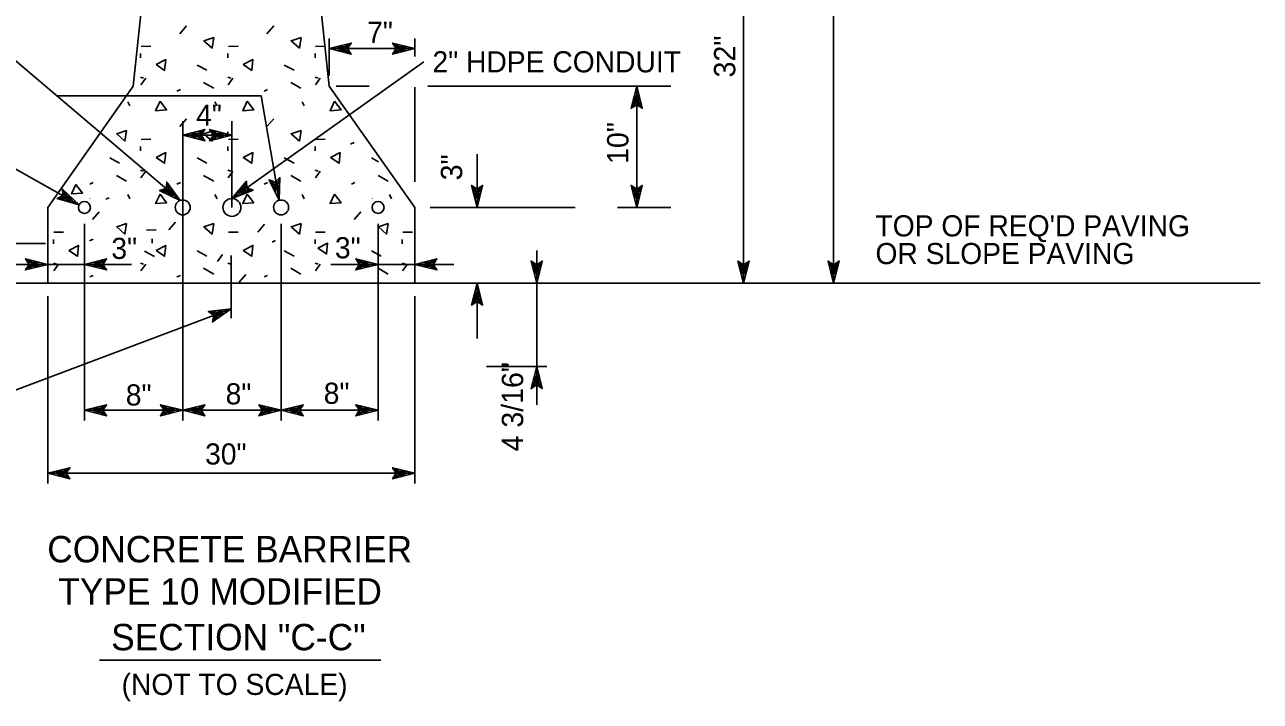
# Model space of a CAD drawing. Extents: x 504255 to 505955, y 659986 to 661086.
# Drawn here: x 505268.3 to 505604.1, y 660605.7 to 660789.5 of the extents above; entities that cross this region are included whole.
import ezdxf

# ---------------------------------------------------------------- set-up
doc = ezdxf.new("R2010")
doc.units = 0
for name, color, linetype in [('Level1', 7, 'Continuous'), ('Level3', 7, 'Continuous'), ('Level63', 7, 'Continuous')]:
    doc.layers.add(name, color=color, linetype=linetype)

msp = doc.modelspace()

# ---------------------------------------------------------------- linework, layer by layer
at = {"layer": 'Level1'}
for p, q in [((505488.16, 660719.36), (505488.16, 660907.77)), ((505463.67, 660719.36), (505463.67, 660835.36)), ((505351.04, 660775.75), (505351.04, 660785.84)), ((505374.31, 660785.84), (505374.31, 660780.88)), ((505262.44, 660782.65), (505310.54, 660741.77)), ((505351.04, 660783.07), (505374.31, 660783.07)), ((505376.79, 660779.49), (505324.64, 660742.31)), ((505352.95, 660772.81), (505361.98, 660772.81)), ((505374.31, 660772.6), (505374.31, 660746.89)), ((505377.92, 660772.81), (505443.93, 660772.81)), ((505434.64, 660739.89), (505434.64, 660772.81)), ((505354.63, 660766.3), (505354.63, 660766.3)), ((505311.27, 660682), (505311.27, 660763.37)), ((505324.64, 660739.89), (505324.64, 660763.37)), ((505249.43, 660759.52), (505283.11, 660740.65)), ((505324.64, 660759.54), (505311.27, 660759.54)), ((505391.27, 660739.89), (505391.27, 660754.35)), ((505374.31, 660738.41), (505374.31, 660738.41)), ((505378.55, 660739.89), (505417.92, 660739.89)), ((505429.39, 660739.89), (505443.93, 660739.89)), ((505284.54, 660682), (505284.54, 660735.45)), ((505338.01, 660682), (505338.01, 660735.45)), ((505364.34, 660682), (505364.34, 660735.45)), ((505407.46, 660686.27), (505407.46, 660728.16)), ((505297.36, 660724.41), (505263.94, 660724.41)), ((505324.44, 660726.81), (505324.44, 660709.79)), ((505351.51, 660724.41), (505384.94, 660724.41)), ((505239.66, 660719.36), (505282.92, 660719.36)), ((505391.27, 660719.36), (505391.27, 660704.33)), ((505274.57, 660664.9), (505274.57, 660715.77)), ((505374.31, 660664.9), (505374.31, 660715.77)), ((505259.16, 660687.76), (505324.42, 660712.31)), ((505393.78, 660696.65), (505410.26, 660696.65)), ((505311.27, 660684.77), (505284.54, 660684.77)), ((505338.01, 660684.77), (505311.27, 660684.77)), ((505364.34, 660684.77), (505338.01, 660684.77)), ((505274.57, 660667.67), (505374.31, 660667.67)), ((505288.64, 660616.89), (505365.15, 660616.89))]:
    msp.add_line(p, q, dxfattribs=at)
for points in [[(505304.18, 660832.53), (505297.84, 660772.81)], [(505344.7, 660832.53), (505351.04, 660772.81)], [(505357.08, 660784.57), (505351.04, 660783.07), (505357.08, 660781.58), (505356.36, 660782.08), (505355.32, 660782.08), (505356.33, 660782.58), (505353.31, 660782.58), (505356, 660783.07), (505353.31, 660783.57), (505356.33, 660783.57), (505355.32, 660784.07), (505356.36, 660784.07), (505357.08, 660784.57), (505356.07, 660783.07), (505357.08, 660781.58)], [(505368.28, 660781.58), (505374.31, 660783.07), (505368.28, 660784.57), (505368.99, 660784.07), (505370.03, 660784.07), (505369.02, 660783.57), (505372.04, 660783.57), (505369.35, 660783.07), (505372.04, 660782.58), (505369.02, 660782.58), (505370.03, 660782.08), (505368.99, 660782.08), (505368.28, 660781.58), (505369.28, 660783.07), (505368.28, 660784.57)], [(505297.84, 660772.81), (505274.57, 660739.89)], [(505351.04, 660772.81), (505374.31, 660739.89)], [(505436.15, 660766.83), (505434.64, 660772.81), (505433.13, 660766.83), (505433.63, 660767.54), (505433.63, 660768.57), (505434.14, 660767.57), (505434.14, 660770.56), (505434.64, 660767.9), (505435.14, 660770.56), (505435.14, 660767.57), (505435.64, 660768.57), (505435.64, 660767.54), (505436.15, 660766.83), (505434.64, 660767.82), (505433.13, 660766.83)], [(505277.01, 660770.26), (505332.55, 660770.26), (505337.48, 660741.84)], [(505317.31, 660761.03), (505311.27, 660759.54), (505317.31, 660758.04), (505316.6, 660758.54), (505315.56, 660758.54), (505316.56, 660759.04), (505313.55, 660759.04), (505316.23, 660759.54), (505313.55, 660760.03), (505316.56, 660760.03), (505315.56, 660760.54), (505316.6, 660760.54), (505317.31, 660761.03), (505316.3, 660759.54), (505317.31, 660758.04)], [(505318.59, 660761.03), (505324.64, 660759.54), (505318.59, 660758.04), (505319.31, 660758.54), (505320.35, 660758.54), (505319.35, 660759.04), (505322.36, 660759.04), (505319.68, 660759.54), (505322.36, 660760.03), (505319.35, 660760.03), (505320.35, 660760.54), (505319.31, 660760.54), (505318.59, 660761.03), (505319.6, 660759.54), (505318.59, 660758.04)], [(505334.75, 660747.37), (505337.48, 660741.84), (505337.7, 660747.99), (505337.36, 660747.2), (505337.57, 660746.19), (505336.87, 660747.07), (505337.5, 660744.14), (505336.45, 660746.64), (505336.52, 660743.92), (505335.89, 660746.86), (505335.61, 660745.78), (505335.39, 660746.78), (505334.75, 660747.37), (505336.43, 660746.72), (505337.7, 660747.99)], [(505277.11, 660742.29), (505283.11, 660740.65), (505278.59, 660744.89), (505278.97, 660744.11), (505279.88, 660743.6), (505278.75, 660743.66), (505281.38, 660742.18), (505278.79, 660743.06), (505280.89, 660741.32), (505278.25, 660742.8), (505278.88, 660741.87), (505277.98, 660742.38), (505277.11, 660742.29), (505278.73, 660743.1), (505278.59, 660744.89)], [(505304.99, 660744.53), (505310.54, 660741.77), (505306.95, 660746.79), (505307.16, 660745.96), (505307.95, 660745.29), (505306.86, 660745.56), (505309.15, 660743.61), (505306.78, 660744.97), (505308.5, 660742.85), (505306.2, 660744.8), (505306.64, 660743.78), (505305.86, 660744.45), (505304.99, 660744.53), (505306.73, 660745.02), (505306.95, 660746.79)], [(505330.41, 660744.6), (505324.64, 660742.31), (505328.64, 660747.02), (505328.35, 660746.21), (505327.51, 660745.6), (505328.63, 660745.78), (505326.18, 660744.02), (505328.65, 660745.19), (505326.76, 660743.22), (505329.22, 660744.98), (505328.69, 660743.99), (505329.53, 660744.6), (505330.41, 660744.6), (505328.72, 660745.23), (505328.64, 660747.02)], [(505389.76, 660745.87), (505391.27, 660739.89), (505392.78, 660745.87), (505392.28, 660745.16), (505392.28, 660744.13), (505391.77, 660745.13), (505391.77, 660742.14), (505391.27, 660744.8), (505390.76, 660742.14), (505390.76, 660745.13), (505390.26, 660744.13), (505390.26, 660745.16), (505389.76, 660745.87), (505391.27, 660744.88), (505392.78, 660745.87)], [(505433.13, 660745.86), (505434.64, 660739.89), (505436.15, 660745.86), (505435.64, 660745.16), (505435.64, 660744.13), (505435.14, 660745.13), (505435.14, 660742.14), (505434.64, 660744.79), (505434.14, 660742.14), (505434.14, 660745.13), (505433.63, 660744.13), (505433.63, 660745.16), (505433.13, 660745.86), (505434.64, 660744.87), (505436.15, 660745.86)], [(505274.57, 660739.89), (505274.57, 660719.36)], [(505374.31, 660739.89), (505374.31, 660719.36)], [(505268.53, 660725.91), (505274.57, 660724.41), (505268.53, 660722.92), (505269.24, 660723.42), (505270.28, 660723.42), (505269.28, 660723.91), (505272.29, 660723.91), (505269.61, 660724.41), (505272.29, 660724.91), (505269.28, 660724.91), (505270.28, 660725.41), (505269.24, 660725.41), (505268.53, 660725.91), (505269.54, 660724.41), (505268.53, 660722.92)], [(505290.58, 660722.92), (505284.54, 660724.41), (505290.58, 660725.91), (505289.87, 660725.41), (505288.82, 660725.41), (505289.83, 660724.91), (505286.81, 660724.91), (505289.5, 660724.41), (505286.81, 660723.91), (505289.83, 660723.91), (505288.82, 660723.42), (505289.87, 660723.42), (505290.58, 660722.92), (505289.57, 660724.41), (505290.58, 660725.91)], [(505358.3, 660722.92), (505364.34, 660724.41), (505358.3, 660725.91), (505359.02, 660725.41), (505360.05, 660725.41), (505359.04, 660724.91), (505362.07, 660724.91), (505359.38, 660724.41), (505362.07, 660723.91), (505359.04, 660723.91), (505360.05, 660723.42), (505359.02, 660723.42), (505358.3, 660722.92), (505359.3, 660724.41), (505358.3, 660725.91)], [(505380.35, 660725.91), (505374.31, 660724.41), (505380.35, 660722.92), (505379.64, 660723.42), (505378.59, 660723.42), (505379.6, 660723.91), (505376.59, 660723.91), (505379.27, 660724.41), (505376.59, 660724.91), (505379.6, 660724.91), (505378.59, 660725.41), (505379.64, 660725.41), (505380.35, 660725.91), (505379.34, 660724.41), (505380.35, 660722.92)], [(505405.95, 660725.33), (505407.46, 660719.36), (505408.97, 660725.33), (505408.47, 660724.63), (505408.47, 660723.59), (505407.97, 660724.59), (505407.97, 660721.6), (505407.46, 660724.26), (505406.96, 660721.6), (505406.96, 660724.59), (505406.45, 660723.59), (505406.45, 660724.63), (505405.95, 660725.33), (505407.46, 660724.33), (505408.97, 660725.33)], [(505462.16, 660725.33), (505463.67, 660719.36), (505465.18, 660725.33), (505464.67, 660724.63), (505464.67, 660723.6), (505464.17, 660724.59), (505464.17, 660721.6), (505463.67, 660724.26), (505463.16, 660721.6), (505463.16, 660724.59), (505462.66, 660723.6), (505462.66, 660724.63), (505462.16, 660725.33), (505463.67, 660724.33), (505465.18, 660725.33)], [(505486.65, 660725.33), (505488.16, 660719.36), (505489.67, 660725.33), (505489.16, 660724.63), (505489.16, 660723.6), (505488.66, 660724.59), (505488.66, 660721.6), (505488.16, 660724.26), (505487.65, 660721.6), (505487.65, 660724.59), (505487.15, 660723.6), (505487.15, 660724.63), (505486.65, 660725.33), (505488.16, 660724.33), (505489.67, 660725.33)], [(505374.31, 660719.36), (505274.57, 660719.36)], [(505392.77, 660713.38), (505391.27, 660719.36), (505389.76, 660713.38), (505390.26, 660714.09), (505390.26, 660715.12), (505390.76, 660714.12), (505390.76, 660717.11), (505391.27, 660714.45), (505391.77, 660717.11), (505391.77, 660714.12), (505392.27, 660715.12), (505392.27, 660714.09), (505392.77, 660713.38), (505391.27, 660714.38), (505389.76, 660713.38)], [(505318.24, 660711.58), (505324.42, 660712.31), (505319.32, 660708.79), (505319.8, 660709.51), (505320.77, 660709.87), (505319.65, 660709.99), (505322.48, 660711.05), (505319.79, 660710.57), (505322.13, 660711.98), (505319.3, 660710.92), (505320.06, 660711.74), (505319.09, 660711.36), (505318.24, 660711.58), (505319.72, 660710.54), (505319.32, 660708.79)], [(505408.97, 660690.67), (505407.46, 660696.65), (505405.95, 660690.67), (505406.45, 660691.38), (505406.45, 660692.42), (505406.96, 660691.42), (505406.96, 660694.41), (505407.46, 660691.75), (505407.97, 660694.41), (505407.97, 660691.42), (505408.47, 660692.42), (505408.47, 660691.38), (505408.97, 660690.67), (505407.46, 660691.67), (505405.95, 660690.67)], [(505290.58, 660686.26), (505284.54, 660684.77), (505290.58, 660683.28), (505289.87, 660683.77), (505288.83, 660683.77), (505289.83, 660684.27), (505286.82, 660684.27), (505289.5, 660684.77), (505286.82, 660685.27), (505289.83, 660685.27), (505288.83, 660685.77), (505289.87, 660685.77), (505290.58, 660686.26), (505289.57, 660684.77), (505290.58, 660683.28)], [(505305.23, 660686.26), (505311.27, 660684.77), (505305.23, 660683.28), (505305.95, 660683.77), (505306.99, 660683.77), (505305.98, 660684.27), (505309, 660684.27), (505306.32, 660684.77), (505309, 660685.27), (505305.98, 660685.27), (505306.99, 660685.77), (505305.95, 660685.77), (505305.23, 660686.26), (505306.24, 660684.77), (505305.23, 660683.28)], [(505317.31, 660686.26), (505311.27, 660684.77), (505317.31, 660683.28), (505316.6, 660683.77), (505315.56, 660683.77), (505316.56, 660684.27), (505313.55, 660684.27), (505316.23, 660684.77), (505313.55, 660685.27), (505316.56, 660685.27), (505315.56, 660685.77), (505316.6, 660685.77), (505317.31, 660686.26), (505316.3, 660684.77), (505317.31, 660683.28)], [(505331.96, 660686.26), (505338.01, 660684.77), (505331.96, 660683.28), (505332.68, 660683.77), (505333.72, 660683.77), (505332.72, 660684.27), (505335.73, 660684.27), (505333.05, 660684.77), (505335.73, 660685.27), (505332.72, 660685.27), (505333.72, 660685.77), (505332.68, 660685.77), (505331.96, 660686.26), (505332.97, 660684.77), (505331.96, 660683.28)], [(505344.04, 660686.26), (505338.01, 660684.77), (505344.04, 660683.28), (505343.33, 660683.77), (505342.29, 660683.77), (505343.3, 660684.27), (505340.28, 660684.27), (505342.96, 660684.77), (505340.28, 660685.27), (505343.3, 660685.27), (505342.29, 660685.77), (505343.33, 660685.77), (505344.04, 660686.26), (505343.03, 660684.77), (505344.04, 660683.28)], [(505358.3, 660686.26), (505364.34, 660684.77), (505358.3, 660683.28), (505359.01, 660683.77), (505360.05, 660683.77), (505359.04, 660684.27), (505362.06, 660684.27), (505359.38, 660684.77), (505362.06, 660685.27), (505359.04, 660685.27), (505360.05, 660685.77), (505359.01, 660685.77), (505358.3, 660686.26), (505359.3, 660684.77), (505358.3, 660683.28)], [(505280.61, 660669.16), (505274.57, 660667.67), (505280.61, 660666.17), (505279.89, 660666.67), (505278.85, 660666.67), (505279.86, 660667.17), (505276.84, 660667.17), (505279.52, 660667.67), (505276.84, 660668.16), (505279.86, 660668.16), (505278.85, 660668.66), (505279.89, 660668.66), (505280.61, 660669.16), (505279.6, 660667.67), (505280.61, 660666.17)], [(505368.28, 660666.17), (505374.31, 660667.67), (505368.28, 660669.16), (505368.99, 660668.66), (505370.03, 660668.66), (505369.02, 660668.16), (505372.04, 660668.16), (505369.35, 660667.67), (505372.04, 660667.17), (505369.02, 660667.17), (505370.03, 660666.67), (505368.99, 660666.67), (505368.28, 660666.17), (505369.28, 660667.67), (505368.28, 660669.16)]]:
    msp.add_lwpolyline(points, dxfattribs=at)
for points in [[(505434.64, 660764.89), (505434.64, 660764.89), (505434.64, 660764.89)], [(505286.1, 660742.45), (505286.1, 660742.44), (505286.1, 660742.45)], [(505362.78, 660742.45), (505362.78, 660742.44), (505362.78, 660742.45)], [(505467.27, 660719.36), (505467.27, 660719.36), (505467.27, 660719.36)]]:
    msp.add_lwpolyline(points, close=True, dxfattribs=at)
at = {"layer": 'Level3'}
for p, q in [((505312.3, 660789.23), (505310.46, 660787.11)), ((505336, 660789.23), (505334.17, 660787.11)), ((505299.84, 660781.72), (505299.84, 660780.53)), ((505302.59, 660783.71), (505299.98, 660783.65)), ((505323.55, 660781.72), (505323.55, 660780.53)), ((505326.3, 660783.71), (505323.68, 660783.65)), ((505347.25, 660781.72), (505347.25, 660780.53)), ((505350, 660783.71), (505347.38, 660783.65)), ((505315.18, 660778.59), (505317.84, 660777.19)), ((505338.88, 660778.59), (505341.54, 660777.19)), ((505300.64, 660775.03), (505299.84, 660775.26)), ((505301.23, 660775.03), (505299.9, 660773.17)), ((505324.33, 660775.03), (505323.55, 660775.26)), ((505324.93, 660775.03), (505323.6, 660773.17)), ((505348.04, 660775.03), (505347.25, 660775.26)), ((505348.63, 660775.03), (505347.31, 660773.17)), ((505309.69, 660771.5), (505310.63, 660771.94)), ((505316.94, 660773.87), (505319.68, 660772.27)), ((505333.39, 660771.5), (505334.33, 660771.94)), ((505340.64, 660773.87), (505343.38, 660772.27)), ((505296.34, 660768.63), (505296.89, 660767.48)), ((505320.04, 660768.63), (505320.59, 660767.48)), ((505343.73, 660768.63), (505344.3, 660767.48)), ((505312.3, 660763.98), (505310.46, 660761.85)), ((505336, 660763.98), (505334.17, 660761.85)), ((505302.59, 660758.45), (505299.98, 660758.4)), ((505323.55, 660760.42), (505323.55, 660759.24)), ((505326.3, 660758.45), (505323.68, 660758.4)), ((505350, 660758.45), (505347.38, 660758.4)), ((505356.89, 660757.11), (505357.83, 660757.54)), ((505299.84, 660756.46), (505299.84, 660755.28)), ((505323.55, 660756.46), (505323.55, 660755.28)), ((505347.25, 660756.46), (505347.25, 660755.28)), ((505291.48, 660753.35), (505294.13, 660751.94)), ((505315.18, 660753.35), (505317.84, 660751.94)), ((505338.88, 660753.35), (505341.54, 660751.94)), ((505362.59, 660753.35), (505364.49, 660752.33)), ((505293.24, 660748.62), (505295.98, 660747.01)), ((505300.64, 660749.78), (505299.84, 660750.01)), ((505301.23, 660749.78), (505299.9, 660747.92)), ((505316.94, 660748.62), (505319.68, 660747.01)), ((505324.33, 660749.78), (505323.55, 660750.01)), ((505324.93, 660749.78), (505323.6, 660747.92)), ((505340.64, 660748.62), (505343.38, 660747.01)), ((505348.04, 660749.78), (505347.25, 660750.01)), ((505348.63, 660749.78), (505347.31, 660747.92)), ((505364.34, 660748.62), (505367.08, 660747.01)), ((505285.99, 660746.25), (505286.93, 660746.68)), ((505309.69, 660746.25), (505310.63, 660746.68)), ((505333.39, 660746.25), (505334.33, 660746.68)), ((505357.1, 660746.25), (505358.03, 660746.68)), ((505290.36, 660742.11), (505291.3, 660742.53)), ((505296.34, 660743.37), (505296.89, 660742.23)), ((505320.04, 660743.37), (505320.59, 660742.23)), ((505343.73, 660743.37), (505344.3, 660742.23)), ((505367.44, 660743.37), (505368, 660742.23)), ((505288.6, 660738.73), (505286.77, 660736.6)), ((505359.7, 660738.73), (505357.87, 660736.6)), ((505304.01, 660733.78), (505301.39, 660733.72)), ((505309.34, 660735.91), (505307.5, 660733.78)), ((505333.51, 660735.32), (505331.69, 660733.2)), ((505276.14, 660731.21), (505276.14, 660730.03)), ((505278.89, 660733.2), (505276.28, 660733.14)), ((505285.98, 660730.85), (505286.91, 660731.28)), ((505303.01, 660731.38), (505303.01, 660730.19)), ((505326.3, 660733.2), (505323.68, 660733.14)), ((505335.58, 660730.46), (505336.52, 660730.89)), ((505347.25, 660731.21), (505347.25, 660730.03)), ((505350, 660733.2), (505347.38, 660733.14)), ((505370.95, 660731.21), (505370.95, 660730.03)), ((505373.7, 660733.2), (505371.08, 660733.14)), ((505300.9, 660728.01), (505303.56, 660726.6)), ((505315.18, 660728.09), (505317.84, 660726.68)), ((505322.04, 660727.08), (505320.71, 660725.23)), ((505338.88, 660728.09), (505341.54, 660726.68)), ((505362.59, 660728.09), (505365.23, 660726.68)), ((505276.94, 660724.52), (505276.14, 660724.76)), ((505277.53, 660724.52), (505276.21, 660722.67)), ((505300.64, 660724.52), (505299.84, 660724.76)), ((505301.23, 660724.52), (505299.9, 660722.67)), ((505324.33, 660724.52), (505323.55, 660724.76)), ((505348.04, 660724.52), (505347.25, 660724.76)), ((505348.63, 660724.52), (505347.31, 660722.67)), ((505371.74, 660724.52), (505370.95, 660724.76)), ((505372.33, 660724.52), (505371.01, 660722.67)), ((505285.99, 660721), (505286.93, 660721.43)), ((505309.69, 660721), (505310.63, 660721.43)), ((505316.94, 660723.36), (505319.68, 660721.76)), ((505328.46, 660721.7), (505326.63, 660719.57)), ((505333.39, 660721), (505334.33, 660721.43)), ((505340.64, 660723.36), (505343.38, 660721.76)), ((505364.34, 660723.36), (505367.08, 660721.76))]:
    msp.add_line(p, q, dxfattribs=at)
for points in [[(505319.73, 660786.07), (505317.04, 660785.17), (505319.26, 660783.19)], [(505343.43, 660786.07), (505340.74, 660785.17), (505342.96, 660783.19)], [(505304.02, 660778.73), (505306.35, 660777.14), (505306.64, 660780.09)], [(505327.72, 660778.73), (505330.05, 660777.14), (505330.33, 660780.09)], [(505305.1, 660768.73), (505303.91, 660766.19), (505306.88, 660766.41)], [(505328.8, 660768.73), (505327.6, 660766.19), (505330.59, 660766.41)], [(505352.5, 660768.73), (505351.31, 660766.19), (505354.29, 660766.41)], [(505296.02, 660760.81), (505293.34, 660759.92), (505295.55, 660757.94)], [(505319.73, 660760.81), (505317.04, 660759.92), (505319.26, 660757.94)], [(505343.43, 660760.81), (505340.74, 660759.92), (505342.96, 660757.94)], [(505304.02, 660753.48), (505306.35, 660751.89), (505306.64, 660754.82)], [(505327.72, 660753.48), (505330.05, 660751.89), (505330.33, 660754.82)], [(505351.43, 660753.48), (505353.75, 660751.89), (505354.03, 660754.82)], [(505282.26, 660746.13), (505281.06, 660743.59), (505284.04, 660743.81)], [(505305.1, 660743.48), (505303.91, 660740.94), (505306.88, 660741.16)], [(505328.8, 660743.48), (505327.6, 660740.94), (505330.59, 660741.16)], [(505352.5, 660743.48), (505351.31, 660740.94), (505354.29, 660741.16)], [(505296.02, 660735.56), (505293.34, 660734.66), (505295.55, 660732.68)], [(505319.73, 660735.56), (505317.04, 660734.66), (505319.26, 660732.68)], [(505343.43, 660735.56), (505340.74, 660734.66), (505342.96, 660732.68)], [(505367.13, 660735.56), (505364.45, 660734.66), (505366.65, 660732.68)], [(505280.32, 660728.23), (505282.65, 660726.64), (505282.94, 660729.58)], [(505304.02, 660728.23), (505306.35, 660726.64), (505306.64, 660729.58)], [(505327.72, 660728.23), (505330.05, 660726.64), (505330.33, 660729.58)], [(505348.02, 660728.84), (505350.35, 660727.25), (505350.63, 660730.19)]]:
    msp.add_lwpolyline(points, close=True, dxfattribs=at)
at = {"layer": 'Level63'}
for p, q in [((505273.95, 660730.1), (505135.43, 660730.1)), ((505274.57, 660719.36), (505604.11, 660719.36))]:
    msp.add_line(p, q, dxfattribs=at)
for centre, major_axis in [((505284.54, 660739.89), (-1.63, 0)), ((505311.27, 660739.89), (-2.04, 0)), ((505324.64, 660739.89), (-2.44, 0)), ((505338, 660739.89), (-2.04, 0)), ((505364.34, 660739.89), (1.63, 0))]:
    msp.add_ellipse(centre, major_axis=major_axis, ratio=0.99, dxfattribs=at)

# ---------------------------------------------------------------- texts
at = {"layer": 'Level1'}
for s, height, p in [('7"', 5.739, (505361.39, 660784.6)), ('2" HDPE CONDUIT', 5.7392, (505379.14, 660776.6)), ('4"', 5.739, (505314.92, 660762.08)), ("TOP OF REQ'D PAVING ", 5.7392, (505499.53, 660732.03)), ('3"', 5.739, (505291.88, 660725.91)), ('3"', 5.739, (505352.63, 660726.08)), ('OR SLOPE PAVING', 5.7392, (505499.53, 660724.5)), ('8"', 5.739, (505295.8, 660686.09)), ('8"', 5.739, (505322.93, 660686.39)), ('8"', 5.739, (505349.59, 660686.54)), ('30"', 5.739, (505317.35, 660670.04)), ('CONCRETE BARRIER', 7.1744, (505274.46, 660643.46)), ('TYPE 10 MODIFIED', 7.1744, (505277.44, 660631.99)), ('SECTION "C-C"', 7.1744, (505291.82, 660619.57)), ('(NOT TO SCALE)', 5.7395, (505294.65, 660607.44))]:
    msp.add_text(s, height=height, dxfattribs=at).set_placement(p)
for s, p in [('32"', (505461.44, 660775.22)), ('10"', (505432.39, 660751.72)), ('3"', (505387.22, 660747.26)), ('4 3/16"', (505403.78, 660673.59))]:
    msp.add_text(s, height=5.797, rotation=90, dxfattribs=at).set_placement(p)

doc.saveas('drawing.dxf')
